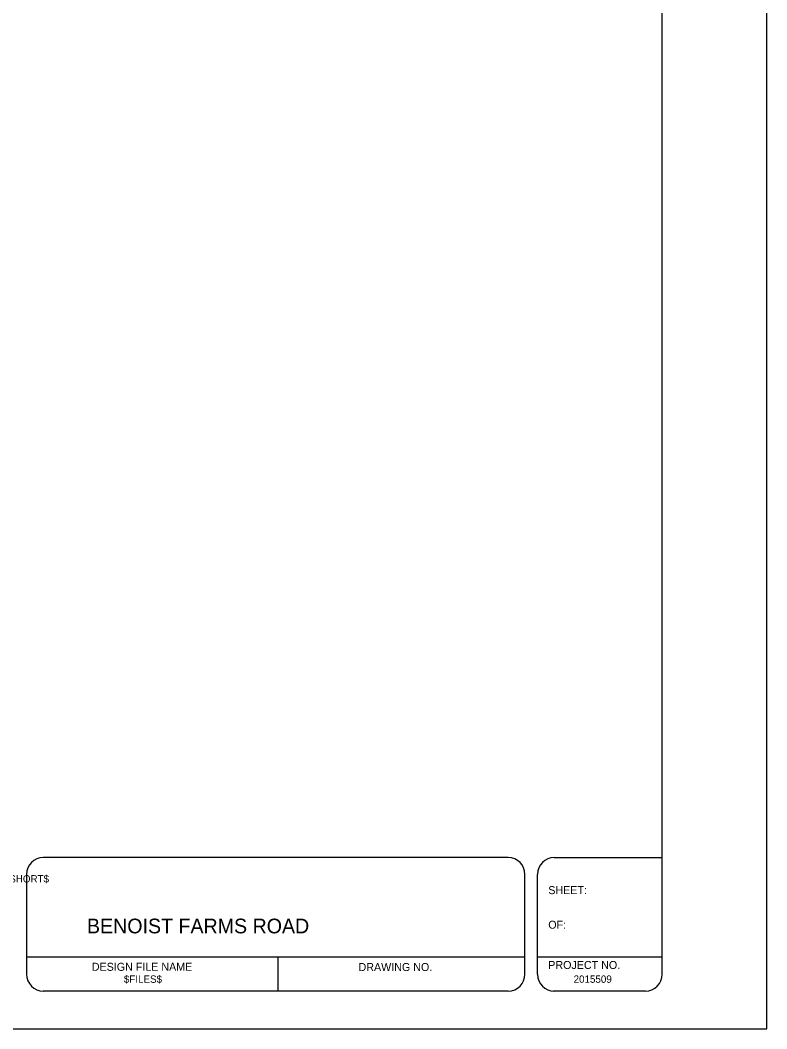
# Model space of a CAD drawing. Extents: x -1.5 to 15.2, y -6.5 to 4.1.
# Drawn here: x 11.28 to 15.2, y -6.49 to -1.19 of the extents above; entities that cross this region are included whole.
import ezdxf

# ---------------------------------------------------------------- set-up
doc = ezdxf.new("R2010")
doc.units = 0
doc.layers.add('Default', color=7, linetype='Continuous')
doc.layers.add('PlotBorder_dp', color=7, linetype='Continuous')

msp = doc.modelspace()

# ---------------------------------------------------------------- linework, layer by layer
at = {"layer": 'Default'}
for p, q in [((14.6515, -6.2034), (14.6515, 3.9164)), ((13.8413, -5.5901), (11.3974, -5.5901)), ((14.0838, -5.5901), (14.6515, -5.5901)), ((11.3092, -5.6783), (11.3092, -6.2032)), ((13.9295, -6.2036), (13.9295, -5.6785)), ((13.9956, -6.2036), (13.9956, -5.6785)), ((13.9284, -6.1142), (11.3083, -6.1142)), ((12.6315, -6.2905), (12.6315, -6.1142)), ((14.6515, -6.1142), (13.9989, -6.1142)), ((13.8413, -6.2915), (11.3974, -6.2915)), ((14.5632, -6.2916), (14.0785, -6.2916))]:
    msp.add_line(p, q, dxfattribs=at)
for centre, major_axis, start_param, end_param in [((11.3974, -5.6783), (0, 0.0882), 0, 1.570796), ((13.8413, -5.6785), (0, 0.0882), 4.712389, 6.283185), ((14.0838, -5.6785), (0, -0.0882), 3.141593, 4.712389), ((11.3974, -6.2032), (0, -0.0882), 4.712389, 6.283185), ((13.8413, -6.2032), (0, 0.0882), 3.141593, 4.712389), ((14.0838, -6.2036), (0, -0.0882), 4.712389, 6.283185), ((14.5632, -6.2034), (0, -0.0882), 0, 1.570796)]:
    msp.add_ellipse(centre, major_axis=major_axis, ratio=0.999927, start_param=start_param, end_param=end_param, dxfattribs=at)
at = {"layer": 'PlotBorder_dp'}
msp.add_lwpolyline([(-1.2985, -6.4901), (15.2015, -6.4901), (15.2015, 4.1099), (-1.2985, 4.1099)], close=True, dxfattribs=at)
msp.add_lwpolyline([(-1.2985, -6.4901), (15.2015, -6.4901), (15.2015, 4.1099), (-1.2985, 4.1099)], close=True, dxfattribs=at)

# ---------------------------------------------------------------- texts
at = {"layer": 'Default'}
for s, height, p in [('$SCALESHORT$', 0.038546, (11.0206, -5.7212)), ('SHEET:', 0.04207, (14.0523, -5.7823)), ('   BENOIST FARMS ROAD   ', 0.077091, (11.541, -5.9883)), ('OF:', 0.04207, (14.0523, -5.964)), ('DESIGN FILE NAME', 0.042066, (11.6524, -6.1852)), ('DRAWING NO.', 0.042066, (13.0549, -6.1865)), ('PROJECT NO.', 0.042066, (14.0523, -6.1757)), ('$FILES$', 0.03855, (11.8209, -6.2482)), ('2015509', 0.03855, (14.1855, -6.2482))]:
    msp.add_text(s, height=height, dxfattribs=at).set_placement(p)

doc.saveas('drawing.dxf')
